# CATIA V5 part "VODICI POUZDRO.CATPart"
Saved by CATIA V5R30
Part number: VODICI POUZDRO
Bounding box of the stored display mesh (mm): x 0 to 27, y -15.5 to 15.5, z -15.5 to 15.5
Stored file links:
  C:\Users\ondra\Desktop\PŘÍLOHA P III\CATIA\VODICI POUZDRO.CATPart
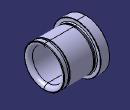
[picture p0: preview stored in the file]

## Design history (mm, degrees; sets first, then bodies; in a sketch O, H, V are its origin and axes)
Set1
  DatumSurface1 to DatumSurface29 "Z11/27x2"
  Join1: Elements (DatumSurface1; DatumSurface2; DatumSurface3; DatumSurface4; DatumSurface5; DatumSurface6; DatumSurface7; DatumSurface8; DatumSurface9; DatumSurface10; DatumSurface11; DatumSurface12; DatumSurface13; DatumSurface14; DatumSurface15; DatumSurface16; DatumSurface17; DatumSurface18; DatumSurface19; DatumSurface20; DatumSurface21; DatumSurface22; DatumSurface23; DatumSurface24; DatumSurface25; DatumSurface26; DatumSurface27; DatumSurface28; DatumSurface29)
Body1 (main body)
  CloseSurface1: CloseElement Join1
